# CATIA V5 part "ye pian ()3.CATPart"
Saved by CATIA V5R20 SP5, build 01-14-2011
Part number: fengshan2
Bounding box of the stored display mesh (mm): x 0 to 148.055, y -45.058 to 54.981, z -2 to 2
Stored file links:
  E:\姜浩然03.08\创意作品\ye pian ()3.CATPart
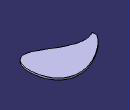
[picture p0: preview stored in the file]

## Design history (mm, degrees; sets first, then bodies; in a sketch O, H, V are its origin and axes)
Body1 (main body)
  Sketch1 on xy-plane, origin (0, 0, 0), H (1, 0, 0), V (0, 1, 0)
    spline S1 through (0, 0) (31.2545, 30.6484) (138.3395, 30.6484) (135.7777, -41.3753) (59.4348, -14.558) (0, -10.4715)
    spline S2 through (0, -10.4715) (0, 0)
    point P1 (0, 0)
    point P2 (0, -10.4715)
    point P3 (0, -10.4715)
    point P4 (0, 0)
    coincidence: P1 O, P2 V, P3 P2, P4 O
  Pad1: profile Sketch1, direction (0, 0, 1), length 1, mirrored extent
  Thickness1: Face end face of Pad1, Thickness 1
